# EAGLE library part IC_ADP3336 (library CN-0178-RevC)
Small, Adjustable Output, 500 mA anyCAP® Low Dropout Regulator
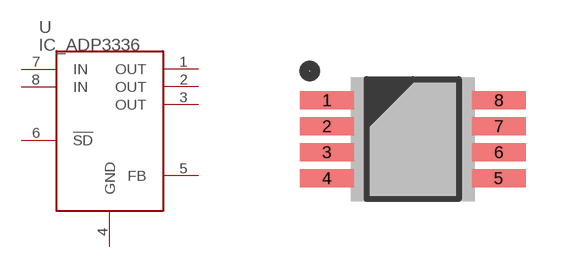
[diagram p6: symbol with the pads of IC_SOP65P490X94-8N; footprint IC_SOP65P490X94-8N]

Designator prefix U

## IC_ADP3336_TSSOP8  [IC_SOP65P490X94-8N]
1  OUT  pas
2  OUT  pas
3  OUT  pas
4  GND  pas
5  FB  pas
6  !SD  pas
7  IN  pas
8  IN  pas

## Footprint IC_SOP65P490X94-8N (pad centres in mm)
(TSSOP-8) 0.65mm pitch; 3.00mm W X 3.00mm L X 0.94mm H body; JEDEC-MO-187AA-T
smd 1.35 x 0.45: 1 -2.15,0.975; 2 -2.15,0.325; 3 -2.15,-0.325; 4 -2.15,-0.975; 5 2.15,-0.975; 6 2.15,-0.325; 7 2.15,0.325; 8 2.15,0.975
